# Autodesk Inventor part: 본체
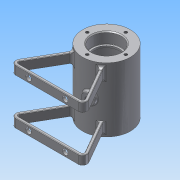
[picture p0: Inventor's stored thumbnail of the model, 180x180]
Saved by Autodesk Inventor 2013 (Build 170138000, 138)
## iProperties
Created: 2016-03
Part Number: 본체
Material: 알루미늄 6061
Document SubType Name: Modeling
Designer: Administrator
Density: 2.71 g/cm^3
Mass: 213.164 g
Surface Area: 334.011 cm^2
Volume: 78.6582 cm^3
Author: Administrator
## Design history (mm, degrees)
sketch "스케치1"
  geometry: C1 r 26 at (0, 0); 1 further point
  constraints: 1 centre point, 1 coincident
  dimensions: "d0" = 52 diameter of C1
extrude "돌출1" new body sketch "스케치1" stored distance "d1" = 70; taper "d2" = 0 deg
node "작업 평면1"
sketch "스케치2"
  geometry: L1 (0, 0)-(0, -65); L2 (-42.594, -65)-(42.594, -65); L3 (42.594, -65)-(0, 8.775); L4 (42.594, -65)-(94.556, -65); L5 (-42.594, -65)-(0, 8.775); C1 r 26 at (0, 0) reference
  constraints: 10 end point, 1 horizontal, 1 midpoint, 1 perpendicular, 1 vertical, 1 other
  dimensions: "d4" = 65 distance of L1.end L1.start; "d5" = 120 deg angle of L4 L3; "d7" = 85.18802 distance of L2.start L2.end
feature "리브1" sketch "스케치2" dims "d8" = 3, "d9" = 10, "d10" = 0, "d11" = 0, "d12" = 1, "d13" = 1
fillet "모깎기1" dims "d14" = 5
fillet "모깎기2" dims "d15" = 2
sketch "스케치3"
  geometry: C1 r 21 at (0, 0); 1 further point
  constraints: 1 centre point, 1 coincident
  dimensions: "d16" = 42 diameter of C1
extrude "돌출2" cut sketch "스케치3" stored distance "d17" = 42; taper "d18" = 0 deg
hole "구멍1" diameter "d21" = 28; stored, may be unused: countersink angle "d25" = 90 deg, drill point angle "d27" = 118 deg; dims "d19" = 10, "d20" = 10, "d22" = 6, "d23" = 32, "d24" = 12, "d26" = 8
sketch "스케치4"
  geometry: C1 r 14 at (0, 0) reference; C2 r 26 at (0, 0) reference; C3 r 16 at (0, 0)
  constraints: 1 centre point, 1 coincident
  dimensions: "d28" = 32 diameter of C3
extrude "돌출3" cut sketch "스케치4" distance "d29" = 12; taper "d30" = 0 deg
fillet "모깎기3" dims "d31" = 3
fillet "모깎기4" dims "d32" = 0.3
fillet "모깎기5" dims "d33" = 3
fillet "모깎기6" dims "d34" = 3
fillet "모깎기7" dims "d35" = 0.5
node "작업 평면2"
sketch "스케치5"
  geometry: C1 r 5 at (0, 0); 1 further point
  constraints: 1 centre point, 1 coincident
  dimensions: "d37" = 10 diameter of C1
extrude "돌출4" join sketch "스케치5" stored distance "d38" = 12; taper "d39" = 0 deg
sketch "스케치6"
  geometry: C1 r 5 at (0, 0) reference; 1 further point
  constraints: 1 coincident
hole "구멍2" sketch "스케치6" at (0, 0) diameter "d40" = 5.188; stored, may be unused: countersink angle "d44" = 90 deg, drill point angle "d46" = 118 deg; dims "d41" = 6, "d42" = 32, "d43" = 12, "d45" = 8
fillet "모깎기8" dims "d47" = 2
sketch "스케치7"
  geometry: L1 (0, 0)-(7.506, -28.012); L2 (0, 0)-(29, 0)
  constraints: 4 end point, 1 equal length, 1 horizontal
  dimensions: "d48" = 29 distance of L1.start L1.end; "d49" = 75 deg angle of L1 L2
node "작업 평면3"
sketch "스케치8"
  geometry: C1 r 6 at (0, 0); 1 further point
  constraints: 1 centre point, 1 coincident
  dimensions: "d50" = 12 diameter of C1
extrude "돌출5" join sketch "스케치8" stored distance "d51" = 12; taper "d52" = 0 deg
hole "구멍3" diameter "d55" = 5.188; stored, may be unused: countersink angle "d59" = 90 deg, drill point angle "d61" = 118 deg; dims "d53" = 10, "d54" = 10, "d56" = 6, "d57" = 32, "d58" = 12, "d60" = 8
fillet "모깎기9" dims "d62" = 2
chamfer "모따기1" distance "d63" = 1; stored, may be unused: second distance "d64" = 2, angle "d65" = 45 deg
sketch "스케치9"
  geometry: C1 r 26 at (0, 0) reference; 1 further point
  constraints: 1 vertical alignment
  dimensions: "d66" = 21 distance of C1.centre point (0, 21)
hole "구멍4" sketch "스케치9" at (0, 21) diameter "d67" = 3.242; stored, may be unused: countersink angle "d71" = 90 deg, drill point angle "d73" = 118 deg; dims "d68" = 8, "d69" = 32, "d70" = 12, "d72" = 10
node "작업 평면4"
sketch "스케치10"
  geometry: 2 further points
  constraints: 1 coincident, 1 other
feature "엠보싱1" sketch "스케치10" dims "d15" = 2, "d77" = 0.5, "d78" = 0
sketch "스케치11"
  geometry: L1 (0, 0)-(0, 9) reference; L2 (0, -50)-(67.868, -50) reference; L3 (0, -41)-(0, -50) reference; L4 (67.868, -41)-(0, -41) reference; L5 (67.868, -50)-(67.868, -41) reference; 7 further points
  constraints: 4 horizontal alignment, 2 midpoint
  dimensions: "d79" = 20 horizontal distance of point (33.934, -20.5) point (13.934, -45.5); "d80" = 20 horizontal distance of point (53.934, -45.5) point (33.934, -20.5); "d81" = 20 horizontal distance of point (53.934, 4.5) point (33.934, -20.5); "d82" = 20 horizontal distance of point (13.934, 4.5) point (33.934, -20.5)
hole "구멍5" sketch "스케치11" at (13.934, 4.5), (53.934, 4.5), (13.934, -45.5), (53.934, -45.5) diameter "d83" = 6; stored, may be unused: countersink angle "d87" = 90 deg, drill point angle "d89" = 118 deg; dims "d84" = 8, "d85" = 32, "d86" = 12, "d88" = 10
node "솔리드1"
mirror "대칭1"
pattern_circular "원형 패턴1" dims angle "d75" = 360 deg
mirror "대칭2"
node "투영된 루프1"
node "투영된 루프2"
other parameters: "d3" = 25, "d36" = 29
